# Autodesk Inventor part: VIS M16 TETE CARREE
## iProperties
Created: 2004-11
Part Number: VIS M16 TETE CARREE
Document SubType Name: Modeling
Designer: Bruno
Manufacturer: Standard
Standards Organization: Custom
Author: Bruno
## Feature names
1. Base1
